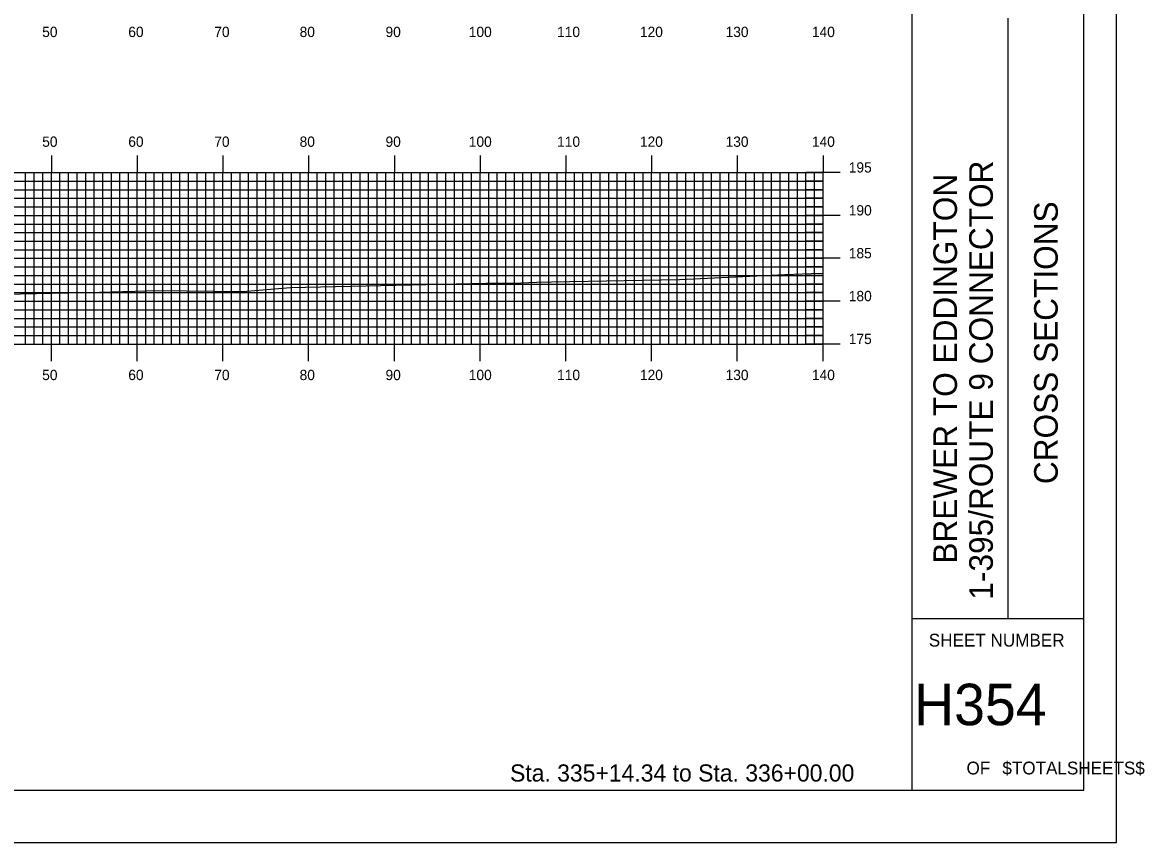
# Model space of a CAD drawing. Extents: x 1823573 to 1823916, y 442591 to 442811.
# Drawn here: x 1823784.9 to 1823915.8, y 442590.5 to 442686.2 of the extents above; entities that cross this region are included whole.
import ezdxf

# ---------------------------------------------------------------- set-up
doc = ezdxf.new("R2010")
doc.units = 0
for name, color, linetype in [('BORDER', 7, 'Continuous'), ('H_V ANNOTATION', 7, 'Continuous'), ('MAJOR', 7, 'Continuous'), ('MINOR', 7, 'Continuous'), ('PLOT BOUNDARY', 7, 'Continuous'), ('S_Roadway_Centerline', 7, 'Continuous')]:
    doc.layers.add(name, color=color, linetype=linetype)

msp = doc.modelspace()

# ---------------------------------------------------------------- linework, layer by layer
at = {"layer": 'BORDER'}
for p, q in [((1823888.71, 442596.67), (1823888.71, 442806.67)), ((1823899.89, 442616.67), (1823899.89, 442686.67)), ((1823888.71, 442616.67), (1823908.71, 442616.67))]:
    msp.add_line(p, q, dxfattribs=at)
msp.add_lwpolyline([(1823588.71, 442596.67), (1823908.71, 442596.67), (1823908.71, 442806.67), (1823588.71, 442806.67)], close=True, dxfattribs=at)
at = {"layer": 'MAJOR'}
for p, q in [((1823788.31, 442670.67), (1823788.31, 442668.67)), ((1823798.31, 442670.67), (1823798.31, 442668.67)), ((1823808.31, 442670.67), (1823808.31, 442668.67)), ((1823818.31, 442670.67), (1823818.31, 442668.67)), ((1823828.31, 442670.67), (1823828.31, 442668.67)), ((1823838.31, 442670.67), (1823838.31, 442668.67)), ((1823848.31, 442670.67), (1823848.31, 442668.67)), ((1823858.31, 442670.67), (1823858.31, 442668.67)), ((1823868.31, 442670.67), (1823868.31, 442668.67)), ((1823878.31, 442670.67), (1823878.31, 442668.67)), ((1823598.31, 442668.67), (1823878.31, 442668.67)), ((1823598.31, 442668.67), (1823878.31, 442668.67)), ((1823788.31, 442648.67), (1823788.31, 442668.67)), ((1823798.31, 442648.67), (1823798.31, 442668.67)), ((1823808.31, 442648.67), (1823808.31, 442668.67)), ((1823818.31, 442648.67), (1823818.31, 442668.67)), ((1823828.31, 442648.67), (1823828.31, 442668.67)), ((1823838.31, 442648.67), (1823838.31, 442668.67)), ((1823848.31, 442648.67), (1823848.31, 442668.67)), ((1823858.31, 442648.67), (1823858.31, 442668.67)), ((1823868.31, 442648.67), (1823868.31, 442668.67)), ((1823880.31, 442668.67), (1823876.3, 442668.67)), ((1823878.31, 442648.67), (1823878.31, 442668.67)), ((1823878.31, 442648.67), (1823878.31, 442668.67)), ((1823598.31, 442663.67), (1823878.31, 442663.67)), ((1823880.31, 442663.67), (1823876.3, 442663.67)), ((1823598.31, 442658.67), (1823878.31, 442658.67)), ((1823880.31, 442658.67), (1823876.3, 442658.67)), ((1823598.31, 442653.67), (1823878.31, 442653.67)), ((1823880.31, 442653.67), (1823876.3, 442653.67)), ((1823598.31, 442648.67), (1823878.31, 442648.67)), ((1823598.31, 442648.67), (1823878.31, 442648.67)), ((1823788.31, 442646.66), (1823788.31, 442648.67)), ((1823798.31, 442646.66), (1823798.31, 442648.67)), ((1823808.31, 442646.66), (1823808.31, 442648.67)), ((1823818.31, 442646.66), (1823818.31, 442648.67)), ((1823828.31, 442646.66), (1823828.31, 442648.67)), ((1823838.31, 442646.66), (1823838.31, 442648.67)), ((1823848.31, 442646.66), (1823848.31, 442648.67)), ((1823858.31, 442646.66), (1823858.31, 442648.67)), ((1823868.31, 442646.66), (1823868.31, 442648.67)), ((1823880.31, 442648.67), (1823876.3, 442648.67)), ((1823878.31, 442646.66), (1823878.31, 442648.67))]:
    msp.add_line(p, q, dxfattribs=at)
at = {"layer": 'MINOR'}
for p, q in [((1823785.31, 442648.67), (1823785.31, 442668.67)), ((1823786.31, 442648.67), (1823786.31, 442668.67)), ((1823787.31, 442648.67), (1823787.31, 442668.67)), ((1823789.31, 442648.67), (1823789.31, 442668.67)), ((1823790.31, 442648.67), (1823790.31, 442668.67)), ((1823791.31, 442648.67), (1823791.31, 442668.67)), ((1823792.31, 442648.67), (1823792.31, 442668.67)), ((1823793.31, 442648.67), (1823793.31, 442668.67)), ((1823794.31, 442648.67), (1823794.31, 442668.67)), ((1823795.31, 442648.67), (1823795.31, 442668.67)), ((1823796.31, 442648.67), (1823796.31, 442668.67)), ((1823797.31, 442648.67), (1823797.31, 442668.67)), ((1823799.31, 442648.67), (1823799.31, 442668.67)), ((1823800.31, 442648.67), (1823800.31, 442668.67)), ((1823801.31, 442648.67), (1823801.31, 442668.67)), ((1823802.31, 442648.67), (1823802.31, 442668.67)), ((1823803.31, 442648.67), (1823803.31, 442668.67)), ((1823804.31, 442648.67), (1823804.31, 442668.67)), ((1823805.31, 442648.67), (1823805.31, 442668.67)), ((1823806.31, 442648.67), (1823806.31, 442668.67)), ((1823807.31, 442648.67), (1823807.31, 442668.67)), ((1823809.31, 442648.67), (1823809.31, 442668.67)), ((1823810.31, 442648.67), (1823810.31, 442668.67)), ((1823811.31, 442648.67), (1823811.31, 442668.67)), ((1823812.31, 442648.67), (1823812.31, 442668.67)), ((1823813.31, 442648.67), (1823813.31, 442668.67)), ((1823814.31, 442648.67), (1823814.31, 442668.67)), ((1823815.31, 442648.67), (1823815.31, 442668.67)), ((1823816.31, 442648.67), (1823816.31, 442668.67)), ((1823817.31, 442648.67), (1823817.31, 442668.67)), ((1823819.31, 442648.67), (1823819.31, 442668.67)), ((1823820.31, 442648.67), (1823820.31, 442668.67)), ((1823821.31, 442648.67), (1823821.31, 442668.67)), ((1823822.31, 442648.67), (1823822.31, 442668.67)), ((1823823.31, 442648.67), (1823823.31, 442668.67)), ((1823824.31, 442648.67), (1823824.31, 442668.67)), ((1823825.31, 442648.67), (1823825.31, 442668.67)), ((1823826.31, 442648.67), (1823826.31, 442668.67)), ((1823827.31, 442648.67), (1823827.31, 442668.67)), ((1823829.31, 442648.67), (1823829.31, 442668.67)), ((1823830.31, 442648.67), (1823830.31, 442668.67)), ((1823831.31, 442648.67), (1823831.31, 442668.67)), ((1823832.31, 442648.67), (1823832.31, 442668.67)), ((1823833.31, 442648.67), (1823833.31, 442668.67)), ((1823834.31, 442648.67), (1823834.31, 442668.67)), ((1823835.31, 442648.67), (1823835.31, 442668.67)), ((1823836.31, 442648.67), (1823836.31, 442668.67)), ((1823837.31, 442648.67), (1823837.31, 442668.67)), ((1823839.31, 442648.67), (1823839.31, 442668.67)), ((1823840.31, 442648.67), (1823840.31, 442668.67)), ((1823841.31, 442648.67), (1823841.31, 442668.67)), ((1823842.31, 442648.67), (1823842.31, 442668.67)), ((1823843.31, 442648.67), (1823843.31, 442668.67)), ((1823844.31, 442648.67), (1823844.31, 442668.67)), ((1823845.31, 442648.67), (1823845.31, 442668.67)), ((1823846.31, 442648.67), (1823846.31, 442668.67)), ((1823847.31, 442648.67), (1823847.31, 442668.67)), ((1823849.31, 442648.67), (1823849.31, 442668.67)), ((1823850.31, 442648.67), (1823850.31, 442668.67)), ((1823851.31, 442648.67), (1823851.31, 442668.67)), ((1823852.31, 442648.67), (1823852.31, 442668.67)), ((1823853.31, 442648.67), (1823853.31, 442668.67)), ((1823854.31, 442648.67), (1823854.31, 442668.67)), ((1823855.31, 442648.67), (1823855.31, 442668.67)), ((1823856.31, 442648.67), (1823856.31, 442668.67)), ((1823857.31, 442648.67), (1823857.31, 442668.67)), ((1823859.31, 442648.67), (1823859.31, 442668.67)), ((1823860.31, 442648.67), (1823860.31, 442668.67)), ((1823861.31, 442648.67), (1823861.31, 442668.67)), ((1823862.31, 442648.67), (1823862.31, 442668.67)), ((1823863.31, 442648.67), (1823863.31, 442668.67)), ((1823864.31, 442648.67), (1823864.31, 442668.67)), ((1823865.31, 442648.67), (1823865.31, 442668.67)), ((1823866.31, 442648.67), (1823866.31, 442668.67)), ((1823867.31, 442648.67), (1823867.31, 442668.67)), ((1823869.31, 442648.67), (1823869.31, 442668.67)), ((1823870.31, 442648.67), (1823870.31, 442668.67)), ((1823871.31, 442648.67), (1823871.31, 442668.67)), ((1823872.31, 442648.67), (1823872.31, 442668.67)), ((1823873.31, 442648.67), (1823873.31, 442668.67)), ((1823874.31, 442648.67), (1823874.31, 442668.67)), ((1823875.31, 442648.67), (1823875.31, 442668.67)), ((1823876.31, 442648.67), (1823876.31, 442668.67)), ((1823877.31, 442648.67), (1823877.31, 442668.67)), ((1823598.31, 442667.67), (1823878.31, 442667.67)), ((1823598.31, 442666.67), (1823878.31, 442666.67)), ((1823878.31, 442667.67), (1823876.3, 442667.67)), ((1823878.31, 442666.67), (1823876.3, 442666.67)), ((1823598.31, 442665.67), (1823878.31, 442665.67)), ((1823878.31, 442665.67), (1823876.3, 442665.67)), ((1823598.31, 442664.67), (1823878.31, 442664.67)), ((1823878.31, 442664.67), (1823876.3, 442664.67)), ((1823598.31, 442662.67), (1823878.31, 442662.67)), ((1823878.31, 442662.67), (1823876.3, 442662.67)), ((1823598.31, 442661.67), (1823878.31, 442661.67)), ((1823878.31, 442661.67), (1823876.3, 442661.67)), ((1823598.31, 442660.67), (1823878.31, 442660.67)), ((1823878.31, 442660.67), (1823876.3, 442660.67)), ((1823598.31, 442659.67), (1823878.31, 442659.67)), ((1823878.31, 442659.67), (1823876.3, 442659.67)), ((1823598.31, 442657.67), (1823878.31, 442657.67)), ((1823878.31, 442657.67), (1823876.3, 442657.67)), ((1823598.31, 442656.67), (1823878.31, 442656.67)), ((1823878.31, 442656.67), (1823876.3, 442656.67)), ((1823598.31, 442655.67), (1823878.31, 442655.67)), ((1823878.31, 442655.67), (1823876.3, 442655.67)), ((1823598.31, 442654.67), (1823878.31, 442654.67)), ((1823878.31, 442654.67), (1823876.3, 442654.67)), ((1823598.31, 442652.67), (1823878.31, 442652.67)), ((1823878.31, 442652.67), (1823876.3, 442652.67)), ((1823598.31, 442651.67), (1823878.31, 442651.67)), ((1823878.31, 442651.67), (1823876.3, 442651.67)), ((1823598.31, 442650.67), (1823878.31, 442650.67)), ((1823598.31, 442649.67), (1823878.31, 442649.67)), ((1823878.31, 442650.67), (1823876.3, 442650.67)), ((1823878.31, 442649.67), (1823876.3, 442649.67))]:
    msp.add_line(p, q, dxfattribs=at)
at = {"layer": 'PLOT BOUNDARY'}
msp.add_lwpolyline([(1823572.52, 442590.55), (1823912.52, 442590.55), (1823912.52, 442810.55), (1823572.52, 442810.55)], close=True, dxfattribs=at)
at = {"layer": 'S_Roadway_Centerline'}
msp.add_lwpolyline([(1823777.31, 442654.36), (1823793.94, 442654.73), (1823800.77, 442654.93), (1823810.62, 442654.8), (1823816.2, 442655.27), (1823839.03, 442655.77), (1823843.05, 442655.81), (1823844.91, 442655.89), (1823846.62, 442655.92), (1823861.55, 442656.2), (1823873.86, 442656.8), (1823877.98, 442656.92), (1823878.31, 442656.91)], dxfattribs=at)

# ---------------------------------------------------------------- texts
at = {"layer": 'BORDER'}
for s, p in [('1-395/ROUTE 9 CONNECTOR', (1823898.11, 442618.87)), ('BREWER TO EDDINGTON', (1823893.93, 442623.07)), ('CROSS SECTIONS', (1823905.68, 442632.34))]:
    msp.add_text(s, height=2.7557, rotation=90, dxfattribs=at).set_placement(p)
for s, height, p in [('SHEET NUMBER', 1.4905, (1823890.64, 442613.4)), ('H354', 4.839, (1823888.92, 442604.23)), ('OF', 1.491, (1823895.04, 442598.49)), ('$TOTALSHEETS$', 1.4905, (1823899.22, 442598.49))]:
    msp.add_text(s, height=height, dxfattribs=at).set_placement(p)
at = {"layer": 'H_V ANNOTATION'}
for s, height, p in [('50', 1.2, (1823787.24, 442684.47)), ('60', 1.2, (1823797.28, 442684.47)), ('70', 1.2, (1823807.31, 442684.47)), ('80', 1.2, (1823817.26, 442684.47)), ('90', 1.2, (1823827.28, 442684.47)), ('100', 1.2, (1823836.99, 442684.47)), ('110', 1.2, (1823847.29, 442684.47)), ('120', 1.2, (1823856.95, 442684.47)), ('130', 1.2, (1823866.94, 442684.47)), ('140', 1.2, (1823877.01, 442684.47)), ('50', 1.2, (1823787.24, 442671.67)), ('60', 1.2, (1823797.28, 442671.67)), ('70', 1.2, (1823807.31, 442671.67)), ('80', 1.2, (1823817.26, 442671.67)), ('90', 1.2, (1823827.28, 442671.67)), ('100', 1.2, (1823836.99, 442671.67)), ('110', 1.2, (1823847.29, 442671.67)), ('120', 1.2, (1823856.95, 442671.67)), ('130', 1.2, (1823866.94, 442671.67)), ('140', 1.2, (1823877.01, 442671.67)), ('195', 1.2, (1823881.31, 442668.67)), ('190', 1.2, (1823881.31, 442663.67)), ('185', 1.2, (1823881.31, 442658.67)), ('180', 1.2, (1823881.31, 442653.67)), ('175', 1.2, (1823881.31, 442648.67)), ('50', 1.2, (1823787.24, 442644.47)), ('60', 1.2, (1823797.28, 442644.47)), ('70', 1.2, (1823807.31, 442644.47)), ('80', 1.2, (1823817.26, 442644.47)), ('90', 1.2, (1823827.28, 442644.47)), ('100', 1.2, (1823836.99, 442644.47)), ('110', 1.2, (1823847.29, 442644.47)), ('120', 1.2, (1823856.95, 442644.47)), ('130', 1.2, (1823866.94, 442644.47)), ('140', 1.2, (1823877.01, 442644.47)), ('Sta. 335+14.34 to Sta. 336+00.00', 2.0004, (1823841.8, 442597.66))]:
    msp.add_text(s, height=height, dxfattribs=at).set_placement(p)

doc.saveas('drawing.dxf')
